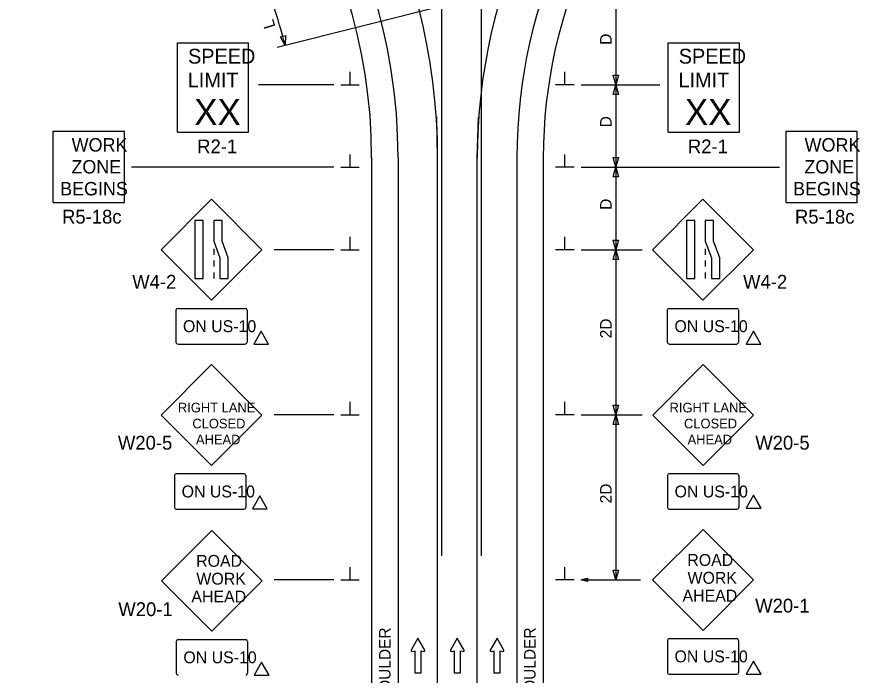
# Model space of a CAD drawing. Extents: x 16728 to 18475, y 6981 to 8243.
# Drawn here: x 16739 to 17250, y 7410 to 7809 of the extents above; entities that cross this region are included whole.
import ezdxf

# ---------------------------------------------------------------- set-up
doc = ezdxf.new("R2010")
doc.units = 0
for name, color, linetype in [('ALI_LEGAL_EX', 7, 'Continuous'), ('MT_SCRATCH_LEVEL_E', 7, 'Continuous'), ('PAVT_EDGE_EX', 7, 'Continuous'), ('TRAFFIC_SIGNS_PR', 7, 'Continuous'), ('TYPICAL_TEXT_DIMEN_PR', 7, 'Continuous')]:
    doc.layers.add(name, color=color, linetype=linetype)

msp = doc.modelspace()

# ---------------------------------------------------------------- linework, layer by layer
at = {"layer": 'ALI_LEGAL_EX'}
for p, q in [((16995.95, 8243.16), (16995.95, 7482.4)), ((17019.95, 8243.16), (17019.95, 7482.4)), ((16993.65, 7350.77), (16993.65, 7723.56)), ((17017.65, 7350.77), (17017.65, 7723.56))]:
    msp.add_line(p, q, dxfattribs=at)
for points in [[(16993.6, 7723.22), (16993.65, 7723.56), (16993.08, 7748.21)], [(17017.7, 7723.22), (17017.65, 7723.56), (17018.48, 7748.2)], [(16993.65, 7623.22), (16993.65, 7648.22)], [(17017.65, 7623.22), (17017.65, 7648.22)], [(16993.65, 7523.22), (16993.65, 7548.22)], [(17017.65, 7523.22), (17017.65, 7548.22)], [(16993.65, 7423.22), (16993.65, 7448.22)], [(17017.65, 7423.22), (17017.65, 7448.22)]]:
    msp.add_lwpolyline(points, dxfattribs=at)
for centre, radius, start, end in [((16629.65, 7723.56), 364, 0, 57.2958), ((17357.65, 7723.56), 340, 129.5666, 180)]:
    msp.add_arc(centre, radius, start, end, dxfattribs=at)
at = {"layer": 'MT_SCRATCH_LEVEL_E'}
for p, q in [((16981.67, 7432.34), (16977.55, 7425.1)), ((16981.67, 7432.34), (16977.55, 7425.1)), ((16985.81, 7425.1), (16981.67, 7432.34)), ((16985.81, 7425.1), (16981.67, 7432.34)), ((17005.57, 7432.34), (17001.46, 7425.1)), ((17005.57, 7432.34), (17001.46, 7425.1)), ((17009.72, 7425.1), (17005.57, 7432.34)), ((17009.72, 7425.1), (17005.57, 7432.34)), ((17029.62, 7432.34), (17025.51, 7425.1)), ((17029.62, 7432.34), (17025.51, 7425.1)), ((17033.77, 7425.1), (17029.62, 7432.34)), ((17033.77, 7425.1), (17029.62, 7432.34)), ((16978.04, 7424.42), (16979.81, 7424.73)), ((16978.04, 7424.42), (16979.81, 7424.73)), ((16979.81, 7424.73), (16979.81, 7411.48)), ((16979.81, 7424.73), (16979.81, 7411.48)), ((16983.56, 7411.48), (16983.56, 7424.73)), ((16983.56, 7424.73), (16985.33, 7424.42)), ((16983.56, 7411.48), (16983.56, 7424.73)), ((16983.56, 7424.73), (16985.33, 7424.42)), ((17001.94, 7424.42), (17003.72, 7424.73)), ((17001.94, 7424.42), (17003.72, 7424.73)), ((17003.72, 7424.73), (17003.72, 7411.48)), ((17003.72, 7424.73), (17003.72, 7411.48)), ((17007.46, 7411.48), (17007.46, 7424.73)), ((17007.46, 7424.73), (17009.24, 7424.42)), ((17007.46, 7411.48), (17007.46, 7424.73)), ((17007.46, 7424.73), (17009.24, 7424.42)), ((17025.99, 7424.42), (17027.77, 7424.73)), ((17025.99, 7424.42), (17027.77, 7424.73)), ((17027.77, 7424.73), (17027.77, 7411.48)), ((17027.77, 7424.73), (17027.77, 7411.48)), ((17031.51, 7411.48), (17031.51, 7424.73)), ((17031.51, 7424.73), (17033.29, 7424.42)), ((17031.51, 7411.48), (17031.51, 7424.73)), ((17031.51, 7424.73), (17033.29, 7424.42)), ((16979.81, 7411.48), (16983.56, 7411.48)), ((16979.81, 7411.48), (16983.56, 7411.48)), ((17003.72, 7411.48), (17007.46, 7411.48)), ((17003.72, 7411.48), (17007.46, 7411.48)), ((17027.77, 7411.48), (17031.51, 7411.48)), ((17027.77, 7411.48), (17031.51, 7411.48))]:
    msp.add_line(p, q, dxfattribs=at)
for centre, start, end in [((16977.96, 7424.88), 150.4248, 279.9638), ((16977.96, 7424.88), 150.4248, 279.9638), ((16985.4, 7424.88), 260.0362, 29.7731), ((16985.4, 7424.88), 260.0362, 29.7731), ((17001.87, 7424.88), 150.4248, 279.9638), ((17001.87, 7424.88), 150.4248, 279.9638), ((17009.31, 7424.88), 260.0362, 29.7731), ((17009.31, 7424.88), 260.0362, 29.7731), ((17025.92, 7424.88), 150.4248, 279.9638), ((17025.92, 7424.88), 150.4248, 279.9638), ((17033.36, 7424.88), 260.0362, 29.7731), ((17033.36, 7424.88), 260.0362, 29.7731)]:
    msp.add_arc(centre, 0.463, start, end, dxfattribs=at)
at = {"layer": 'PAVT_EDGE_EX'}
for p, q in [((16953.65, 7723.56), (16953.65, 7350.77)), ((16969.65, 7723.56), (16969.65, 7350.77)), ((17041.65, 7723.56), (17041.65, 7350.77)), ((17057.65, 7723.56), (17057.65, 7350.77))]:
    msp.add_line(p, q, dxfattribs=at)
for centre, radius, start, end in [((16629.65, 7723.56), 340, 0, 70.3484), ((16629.65, 7723.56), 324, 0, 70.3484), ((17357.65, 7723.56), 316, 129.5666, 180), ((17357.65, 7723.56), 300, 129.5666, 180), ((17357.65, 7623.56), 300, 180, 180.00000277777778)]:
    msp.add_arc(centre, radius, start, end, dxfattribs=at)
at = {"layer": 'TRAFFIC_SIGNS_PR'}
for p, q in [((16835.87, 7793.07), (16879.07, 7793.07)), ((16835.87, 7739.07), (16835.87, 7793.07)), ((16879.07, 7739.07), (16879.07, 7793.07)), ((17133.29, 7793.07), (17176.49, 7793.07)), ((17133.29, 7739.07), (17133.29, 7793.07)), ((17176.49, 7739.07), (17176.49, 7793.07)), ((16760.57, 7696.49), (16760.57, 7739.69)), ((16760.57, 7739.69), (16803.77, 7739.69)), ((16803.77, 7696.49), (16803.77, 7739.69)), ((16835.87, 7739.07), (16879.07, 7739.07)), ((17133.29, 7739.07), (17176.49, 7739.07)), ((17204.8, 7696.49), (17204.8, 7739.69)), ((17204.8, 7739.69), (17248, 7739.69)), ((17248, 7696.49), (17248, 7739.69)), ((16856.55, 7698.36), (16826.01, 7667.81)), ((16856.55, 7698.36), (16826.01, 7667.81)), ((16887.1, 7667.81), (16856.55, 7698.36)), ((16887.1, 7667.81), (16856.55, 7698.36)), ((17154.44, 7698.35), (17123.89, 7667.81)), ((17184.99, 7667.81), (17154.44, 7698.35)), ((16760.57, 7696.49), (16803.77, 7696.49)), ((17204.8, 7696.49), (17248, 7696.49)), ((16826.01, 7667.81), (16856.55, 7637.26)), ((16826.01, 7667.81), (16856.55, 7637.26)), ((16856.55, 7637.26), (16887.1, 7667.81)), ((16857.95, 7668.36), (16857.95, 7664.76)), ((17123.89, 7667.81), (17154.44, 7637.26)), ((17154.44, 7637.26), (17184.99, 7667.81)), ((17155.83, 7668.36), (17155.83, 7664.76)), ((16857.95, 7661.16), (16857.95, 7657.56)), ((17155.83, 7661.16), (17155.83, 7657.56)), ((16857.95, 7653.96), (16857.95, 7650.36)), ((17155.83, 7653.96), (17155.83, 7650.36)), ((16834.95, 7631.14), (16834.95, 7611.79)), ((16836.08, 7632.26), (16877.03, 7632.26)), ((16878.15, 7631.14), (16878.15, 7611.79)), ((17132.84, 7631.14), (17132.84, 7611.79)), ((17133.96, 7632.26), (17174.91, 7632.26)), ((17176.04, 7631.14), (17176.04, 7611.79)), ((16836.08, 7610.66), (16877.03, 7610.66)), ((17133.96, 7610.66), (17174.91, 7610.66)), ((16856.55, 7598.19), (16826.01, 7567.64)), ((16887.1, 7567.64), (16856.55, 7598.19)), ((17154.53, 7598.19), (17123.98, 7567.64)), ((17185.07, 7567.64), (17154.53, 7598.19)), ((16826.01, 7567.64), (16856.55, 7537.1)), ((16856.55, 7537.1), (16887.1, 7567.64)), ((17123.98, 7567.64), (17154.53, 7537.1)), ((17154.53, 7537.1), (17185.07, 7567.64)), ((16834.16, 7530.97), (16834.16, 7511.62)), ((16835.28, 7532.1), (16876.23, 7532.1)), ((16877.36, 7530.97), (16877.36, 7511.62)), ((17132.93, 7530.97), (17132.93, 7511.62)), ((17134.05, 7532.1), (17175, 7532.1)), ((17176.13, 7530.97), (17176.13, 7511.62)), ((16835.28, 7510.5), (16876.23, 7510.5)), ((17134.05, 7510.5), (17175, 7510.5)), ((17154.49, 7498.25), (17123.94, 7467.7)), ((17185.03, 7467.7), (17154.49, 7498.25)), ((16856.81, 7497.72), (16826.27, 7467.17)), ((16887.36, 7467.17), (16856.81, 7497.72)), ((16826.27, 7467.17), (16856.81, 7436.62)), ((16856.81, 7436.62), (16887.36, 7467.17)), ((17123.94, 7467.7), (17154.49, 7437.15)), ((17154.49, 7437.15), (17185.03, 7467.7)), ((16836.34, 7431.62), (16877.29, 7431.62)), ((17134.01, 7432.15), (17174.96, 7432.15)), ((16835.21, 7430.5), (16835.21, 7411.15)), ((16878.41, 7430.5), (16878.41, 7411.15)), ((17132.89, 7431.03), (17132.89, 7411.68)), ((17176.08, 7431.03), (17176.08, 7411.68)), ((17134.01, 7410.55), (17174.96, 7410.55))]:
    msp.add_line(p, q, dxfattribs=at)
for points in [[(16846.55, 7685.51), (16846.55, 7650.36), (16851.6, 7650.36), (16851.6, 7685.51)], [(16857.95, 7685.51), (16857.95, 7672.93), (16861.71, 7662.94), (16861.71, 7650.36), (16866.77, 7650.36), (16866.77, 7662.94), (16863, 7672.93), (16863, 7685.51)], [(16857.95, 7685.51), (16857.95, 7672.93), (16861.71, 7662.94), (16861.71, 7650.36), (16866.77, 7650.36), (16866.77, 7662.94), (16863, 7672.93), (16863, 7685.51)], [(17144.43, 7685.51), (17144.43, 7650.36), (17149.49, 7650.36), (17149.49, 7685.51)], [(17155.83, 7685.51), (17155.83, 7672.93), (17159.6, 7662.94), (17159.6, 7650.36), (17164.65, 7650.36), (17164.65, 7662.94), (17160.89, 7672.93), (17160.89, 7685.51)]]:
    msp.add_lwpolyline(points, close=True, dxfattribs=at)
for centre, start, end in [((16836.08, 7631.14), 90, 180), ((16877.03, 7631.14), 0, 90), ((17133.96, 7631.14), 90, 180), ((17174.91, 7631.14), 0, 90), ((16836.08, 7611.79), 180, 270), ((16877.03, 7611.79), 270, 0), ((17133.96, 7611.79), 180, 270), ((17174.91, 7611.79), 270, 0), ((16835.28, 7530.97), 90, 180), ((16876.23, 7530.97), 0, 90), ((17134.05, 7530.97), 90, 180), ((17175, 7530.97), 0, 90), ((16835.28, 7511.62), 180, 270), ((16876.23, 7511.62), 270, 0), ((17134.05, 7511.62), 180, 270), ((17175, 7511.62), 270, 0), ((16836.34, 7430.5), 90, 180), ((16877.29, 7430.5), 0, 90), ((17134.01, 7431.03), 90, 180), ((17174.96, 7431.03), 0, 90), ((16836.34, 7411.15), 180, 270), ((16877.29, 7411.15), 270, 0), ((17134.01, 7411.68), 180, 270), ((17174.96, 7411.68), 270, 0)]:
    msp.add_arc(centre, 1.12, start, end, dxfattribs=at)
at = {"layer": 'TYPICAL_TEXT_DIMEN_PR'}
for p, q in [((17000.16, 7816.27), (16896.42, 7790.32)), ((17101.65, 7817.74), (17101.65, 7767.74)), ((16898.33, 7796.83), (16899.85, 7797.22)), ((16901.28, 7791.53), (16898.33, 7796.83)), ((16899.85, 7797.22), (16901.38, 7797.6)), ((16901.38, 7797.6), (16901.28, 7791.53)), ((16940.52, 7767.74), (16940.52, 7775.53)), ((17070.77, 7767.74), (17070.77, 7775.53)), ((17101.65, 7767.74), (17100.08, 7773.61)), ((17100.08, 7773.61), (17101.65, 7773.61)), ((17101.65, 7773.61), (17103.22, 7773.61)), ((17103.22, 7773.61), (17101.65, 7767.74)), ((16930.65, 7767.74), (16884.99, 7767.74)), ((16934.9, 7767.74), (16946.15, 7767.74)), ((17076.4, 7767.74), (17065.15, 7767.74)), ((17080.65, 7767.74), (17128.35, 7767.74)), ((17100.08, 7761.88), (17101.65, 7767.74)), ((17101.65, 7767.74), (17101.65, 7717.74)), ((17101.65, 7767.74), (17103.22, 7761.88)), ((17101.65, 7761.88), (17100.08, 7761.88)), ((17103.22, 7761.88), (17101.65, 7761.88)), ((16940.52, 7717.74), (16940.52, 7725.53)), ((17070.77, 7717.74), (17070.77, 7725.53)), ((17101.65, 7717.74), (17100.08, 7723.61)), ((17100.08, 7723.61), (17101.65, 7723.61)), ((17101.65, 7723.61), (17103.22, 7723.61)), ((17103.22, 7723.61), (17101.65, 7717.74)), ((16930.65, 7717.74), (16808.04, 7717.74)), ((16934.9, 7717.74), (16946.15, 7717.74)), ((17076.4, 7717.74), (17065.15, 7717.74)), ((17080.65, 7717.74), (17200.8, 7717.74)), ((17100.08, 7711.88), (17101.65, 7717.74)), ((17101.65, 7717.74), (17101.65, 7667.74)), ((17101.65, 7717.74), (17103.22, 7711.88)), ((17101.65, 7711.88), (17100.08, 7711.88)), ((17103.22, 7711.88), (17101.65, 7711.88)), ((16940.52, 7667.74), (16940.52, 7675.53)), ((17070.77, 7667.74), (17070.77, 7675.53)), ((17101.65, 7667.74), (17100.08, 7673.61)), ((17100.08, 7673.61), (17101.65, 7673.61)), ((17101.65, 7673.61), (17103.22, 7673.61)), ((17103.22, 7673.61), (17101.65, 7667.74)), ((16930.65, 7667.74), (16894.65, 7667.74)), ((16934.9, 7667.74), (16946.15, 7667.74)), ((17076.4, 7667.74), (17065.15, 7667.74)), ((17080.65, 7667.74), (17117.56, 7667.74)), ((17100.08, 7661.88), (17101.65, 7667.74)), ((17101.65, 7667.74), (17101.65, 7567.74)), ((17101.65, 7667.74), (17103.22, 7661.88)), ((17101.65, 7661.88), (17100.08, 7661.88)), ((17103.22, 7661.88), (17101.65, 7661.88)), ((16940.52, 7567.74), (16940.52, 7575.53)), ((17070.77, 7567.74), (17070.77, 7575.53)), ((17101.65, 7567.74), (17100.08, 7573.61)), ((17100.08, 7573.61), (17101.65, 7573.61)), ((17101.65, 7573.61), (17103.22, 7573.61)), ((17103.22, 7573.61), (17101.65, 7567.74)), ((16930.65, 7567.74), (16894.65, 7567.74)), ((16934.9, 7567.74), (16946.15, 7567.74)), ((17076.4, 7567.74), (17065.15, 7567.74)), ((17080.65, 7567.74), (17117.56, 7567.74)), ((17100.08, 7561.88), (17101.65, 7567.74)), ((17101.65, 7567.74), (17101.65, 7467.74)), ((17101.65, 7567.74), (17103.22, 7561.88)), ((17101.65, 7561.88), (17100.08, 7561.88)), ((17103.22, 7561.88), (17101.65, 7561.88)), ((16940.52, 7467.74), (16940.52, 7475.53)), ((17070.77, 7467.74), (17070.77, 7475.53)), ((17101.65, 7467.74), (17100.08, 7473.61)), ((17100.08, 7473.61), (17101.65, 7473.61)), ((17101.65, 7473.61), (17103.22, 7473.61)), ((17103.22, 7473.61), (17101.65, 7467.74)), ((16930.65, 7467.74), (16894.65, 7467.74)), ((16934.9, 7467.74), (16946.15, 7467.74)), ((17076.4, 7467.74), (17065.15, 7467.74)), ((17080.65, 7467.74), (17084.56, 7468.79)), ((17080.65, 7467.74), (17116.65, 7467.74)), ((17084.56, 7466.7), (17080.65, 7467.74)), ((17084.56, 7468.79), (17084.56, 7467.74)), ((17084.56, 7467.74), (17084.56, 7466.7))]:
    msp.add_line(p, q, dxfattribs=at)
for points in [[(16886.67, 7618.34), (16882.15, 7610.5), (16891.2, 7610.5)], [(17185.09, 7618.34), (17180.56, 7610.5), (17189.61, 7610.5)], [(16885.88, 7518.58), (16881.35, 7510.75), (16890.4, 7510.75)], [(17185.17, 7519.11), (17180.65, 7511.28), (17189.7, 7511.28)], [(16886.93, 7417.9), (16882.4, 7410.06), (16891.46, 7410.06)], [(17185.13, 7418.43), (17180.61, 7410.59), (17189.66, 7410.59)]]:
    msp.add_lwpolyline(points, close=True, dxfattribs=at)
msp.add_arc((16629.65, 7723.56), 280, 14.0482, 19.32, dxfattribs=at)

# ---------------------------------------------------------------- texts
at = {"layer": 'TRAFFIC_SIGNS_PR'}
for s, height, p in [('SPEED', 9, (16842.36, 7780.54)), ('SPEED', 9, (17139.78, 7780.54)), ('LIMIT', 9, (16842.17, 7766.14)), ('LIMIT', 9, (17139.6, 7766.14)), ('XX', 15.785, (16846.12, 7743.3)), ('XX', 15.785, (17143.54, 7743.3)), ('WORK', 8.119, (16771.82, 7727.28)), ('R2-1', 8.37, (16847.88, 7726.2)), ('R2-1', 8.37, (17145.3, 7726.2)), ('WORK', 8.119, (17216.05, 7727.28)), ('ZONE', 8.119, (16771.68, 7713.99)), ('ZONE', 8.119, (17215.92, 7713.99)), ('BEGINS', 8.119, (16764.85, 7700.71)), ('BEGINS', 8.119, (17209.09, 7700.71)), ('R5-18c', 8.37, (16765.98, 7683.62)), ('R5-18c', 8.37, (17210.21, 7683.62)), ('W4-2', 8.37, (16808.53, 7644.18)), ('W4-2', 8.37, (17178.76, 7644.18)), ('ON US-10', 7.2, (16839.27, 7617.86)), ('ON US-10', 7.2, (17137.16, 7617.86)), ('RIGHT LANE', 5.85, (16836.21, 7569.21)), ('RIGHT LANE', 5.85, (17134.19, 7569.21)), ('CLOSED', 5.85, (16844.98, 7559.54)), ('CLOSED', 5.85, (17142.95, 7559.54)), ('W20-5', 8.37, (16799.85, 7546.65)), ('AHEAD', 5.85, (16847.17, 7549.86)), ('AHEAD', 5.85, (17145.14, 7549.86)), ('W20-5', 8.37, (17186.14, 7546.65)), ('ON US-10', 7.2, (16838.48, 7517.7)), ('ON US-10', 7.2, (17137.24, 7517.7)), ('ROAD', 7.2, (16847.3, 7475.65)), ('ROAD', 7.2, (17144.97, 7476.18)), ('WORK', 7.2, (17145.09, 7465.38)), ('WORK', 7.2, (16847.42, 7464.85)), ('AHEAD', 7.2, (16844.39, 7454.05)), ('AHEAD', 7.2, (17142.06, 7454.57)), ('W20-1', 8.37, (16800.1, 7445.8)), ('W20-1', 8.37, (17186.09, 7447.94)), ('ON US-10', 7.2, (16839.53, 7417.22)), ('ON US-10', 7.2, (17137.2, 7417.75))]:
    msp.add_text(s, height=height, dxfattribs=at).set_placement(p)
at = {"layer": 'TYPICAL_TEXT_DIMEN_PR'}
for s, rotation, p in [('L', 106.685, (16895.4, 7802.91)), ('D', 90, (17099.09, 7791.96)), ('D', 90, (17099.09, 7741.96)), ('D', 90, (17099.09, 7691.96)), ('2D', 90, (17099.09, 7614.11)), ('2D', 90, (17099.09, 7514.11)), ('SHOULDER', 90, (16965.09, 7386.89)), ('SHOULDER', 90, (17052.95, 7386.89))]:
    msp.add_text(s, height=7, rotation=rotation, dxfattribs=at).set_placement(p)

doc.saveas('drawing.dxf')
